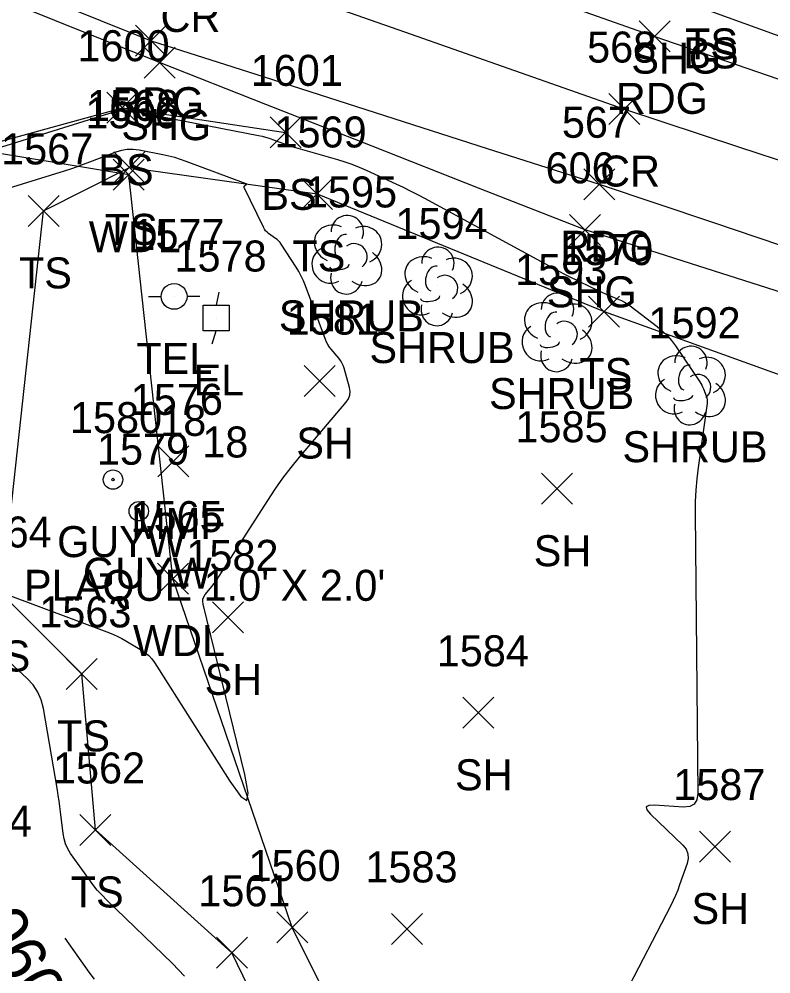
# Model space of a CAD drawing. Extents: x 1592612 to 1596497, y 111838 to 113741.
# Drawn here: x 1592925.8 to 1592974.4, y 113362.1 to 113423.7 of the extents above; entities that cross this region are included whole.
import ezdxf

# ---------------------------------------------------------------- set-up
doc = ezdxf.new("R2010")
doc.units = 0
for name, color, linetype in [('L_A', 7, 'Continuous'), ('L_C', 7, 'Continuous'), ('L_I', 7, 'Continuous'), ('L_TIC', 7, 'Continuous'), ('LAWA', 7, 'Continuous'), ('LELB', 7, 'Continuous'), ('LSH', 7, 'Continuous'), ('LSOGCMA_T', 7, 'Continuous'), ('LSOGCMI', 7, 'Continuous'), ('P_A', 7, 'Continuous'), ('P_I', 7, 'Continuous'), ('P_TIC', 7, 'Continuous'), ('PEU', 7, 'Continuous'), ('PRC', 7, 'Continuous'), ('PSU', 7, 'Continuous'), ('U_A', 7, 'Continuous'), ('U_C', 7, 'Continuous'), ('U_I', 7, 'Continuous'), ('UEPT', 7, 'Continuous'), ('UP', 7, 'Continuous'), ('UPGW', 7, 'Continuous')]:
    doc.layers.add(name, color=color, linetype=linetype)

msp = doc.modelspace()

# ---------------------------------------------------------------- linework, layer by layer
at = {"layer": 'L_TIC'}
for points in [[(1592931.512, 113416.98), (1592933.512, 113418.98)], [(1592933.512, 113416.98), (1592931.512, 113418.98)], [(1592942.04, 113415.39), (1592944.04, 113417.39)], [(1592944.04, 113415.39), (1592942.04, 113417.39)], [(1592931.961, 113413.131), (1592933.961, 113415.131)], [(1592933.961, 113413.131), (1592931.961, 113415.131)], [(1592931.916, 113412.656), (1592933.916, 113414.656)], [(1592933.916, 113412.656), (1592931.916, 113414.656)], [(1592944.073, 113411.416), (1592946.073, 113413.416)], [(1592946.073, 113411.416), (1592944.073, 113413.416)], [(1592926.418, 113410.321), (1592928.418, 113412.321)], [(1592928.418, 113410.321), (1592926.418, 113412.321)], [(1592962.598, 113403.825), (1592964.598, 113405.825)], [(1592964.598, 113403.825), (1592962.598, 113405.825)], [(1592944.244, 113399.341), (1592946.244, 113401.341)], [(1592946.244, 113399.341), (1592944.244, 113401.341)], [(1592934.794, 113394.161), (1592936.794, 113396.161)], [(1592936.794, 113394.161), (1592934.794, 113396.161)], [(1592959.57, 113392.394), (1592961.57, 113394.394)], [(1592961.57, 113392.394), (1592959.57, 113394.394)], [(1592934.771, 113386.596), (1592936.771, 113388.596)], [(1592936.771, 113386.596), (1592934.771, 113388.596)], [(1592938.327, 113384.094), (1592940.327, 113386.094)], [(1592940.327, 113384.094), (1592938.327, 113386.094)], [(1592928.879, 113380.446), (1592930.879, 113382.446)], [(1592930.879, 113380.446), (1592928.879, 113382.446)], [(1592954.49, 113377.937), (1592956.49, 113379.937)], [(1592956.49, 113377.937), (1592954.49, 113379.937)], [(1592929.763, 113370.375), (1592931.763, 113372.375)], [(1592931.763, 113370.375), (1592929.763, 113372.375)], [(1592969.755, 113369.303), (1592971.755, 113371.303)], [(1592971.755, 113369.303), (1592969.755, 113371.303)], [(1592942.474, 113364.084), (1592944.474, 113366.084)], [(1592944.474, 113364.084), (1592942.474, 113366.084)], [(1592949.886, 113363.989), (1592951.886, 113365.989)], [(1592951.886, 113363.989), (1592949.886, 113365.989)], [(1592938.58, 113362.449), (1592940.58, 113364.449)], [(1592940.58, 113362.449), (1592938.58, 113364.449)]]:
    msp.add_lwpolyline(points, dxfattribs=at)
at = {"layer": 'LAWA'}
for points in [[(1592932.916, 113413.656), (1592913.205, 113416.891)], [(1593081.556, 113298.492), (1593031.204, 113311.984), (1593004.196, 113328.084), (1592975.03, 113331.936), (1592955.15, 113341.657), (1592943.474, 113365.084), (1592935.771, 113387.596), (1592932.916, 113413.656)]]:
    msp.add_lwpolyline(points, dxfattribs=at)
at = {"layer": 'LELB'}
for points in [[(1592915.162, 113421.985), (1592920.685, 113414.734), (1592932.512, 113417.98), (1592943.04, 113416.389)], [(1593022.223, 113298.621), (1592996.05, 113319.251), (1592973.737, 113329.884), (1592951.567, 113338.734), (1592939.58, 113363.449), (1592930.763, 113371.375), (1592929.879, 113381.446), (1592924.735, 113386.602), (1592927.418, 113411.322), (1592932.961, 113414.131), (1592945.073, 113412.416), (1592963.598, 113404.825), (1592977.398, 113399.854), (1592996.446, 113393.062), (1593007.402, 113387.97)]]:
    msp.add_lwpolyline(points, dxfattribs=at)
at = {"layer": 'LSH'}
for p, q in [((1592946.979, 113408.545), (1592946.979, 113408.545)), ((1592946.979, 113408.545), (1592946.979, 113408.545)), ((1592952.825, 113406.502), (1592952.825, 113406.502)), ((1592952.825, 113406.502), (1592952.825, 113406.502)), ((1592960.546, 113403.536), (1592960.546, 113403.536)), ((1592960.546, 113403.536), (1592960.546, 113403.536)), ((1592969.157, 113400.107), (1592969.157, 113400.107)), ((1592969.157, 113400.107), (1592969.157, 113400.107))]:
    msp.add_line(p, q, dxfattribs=at)
for centre in [(1592947.025, 113409.979), (1592952.872, 113407.936), (1592960.593, 113404.97), (1592969.204, 113401.541)]:
    msp.add_arc(centre, 1.047, 335.52715, 180.95627, dxfattribs=at)
for centre, major_axis, ratio, start_param, end_param in [((1592946.187, 113409.212), (1.21, -0.512), 0.895232, 1.570796, 4.712389), ((1592948.02, 113409.129), (-1.141, -0.483), 0.949671, 1.570796, 4.712389), ((1592946.77, 113409.004), (-0.208, -0.792), 0.645439, 3.141593, 6.283185), ((1592945.895, 113407.837), (0.584, -1.042), 0.959034, 3.141593, 6.283185), ((1592947.479, 113408.379), (-0.5, 0.667), 0.989748, 3.141593, 6.283185), ((1592947.979, 113407.712), (-1.09, 0.792), 0.841452, 1.570796, 4.712389), ((1592952.033, 113407.168), (1.21, -0.512), 0.895232, 1.570796, 4.712389), ((1592953.867, 113407.085), (-1.141, -0.483), 0.949671, 1.570796, 4.712389), ((1592946.52, 113407.795), (-0.625, -0.083), 0.423636, 0, 3.141593), ((1592952.617, 113406.96), (-0.208, -0.792), 0.645439, 3.141593, 6.283185), ((1592946.979, 113407.045), (0.265, 1.061), 0.942809, 1.570796, 4.712389), ((1592953.325, 113406.335), (-0.5, 0.667), 0.989748, 3.141593, 6.283185), ((1592951.742, 113405.793), (0.584, -1.042), 0.959034, 3.141593, 6.283185), ((1592953.825, 113405.669), (-1.09, 0.792), 0.841452, 1.570796, 4.712389), ((1592952.367, 113405.752), (-0.625, -0.083), 0.423636, 0, 3.141593), ((1592952.825, 113405.002), (0.265, 1.061), 0.942809, 1.570796, 4.712389), ((1592959.754, 113404.203), (1.21, -0.512), 0.895232, 1.570796, 4.712389), ((1592961.588, 113404.12), (-1.141, -0.483), 0.949671, 1.570796, 4.712389), ((1592960.338, 113403.994), (-0.208, -0.792), 0.645439, 3.141593, 6.283185), ((1592959.463, 113402.828), (0.584, -1.042), 0.959034, 3.141593, 6.283185), ((1592961.046, 113403.369), (-0.5, 0.667), 0.989748, 3.141593, 6.283185), ((1592961.546, 113402.703), (-1.09, 0.792), 0.841452, 1.570796, 4.712389), ((1592960.088, 113402.786), (-0.625, -0.083), 0.423636, 0, 3.141593), ((1592960.546, 113402.036), (0.265, 1.061), 0.942809, 1.570796, 4.712389), ((1592968.365, 113400.773), (1.21, -0.512), 0.895232, 1.570796, 4.712389), ((1592970.198, 113400.69), (-1.141, -0.483), 0.949671, 1.570796, 4.712389), ((1592968.948, 113400.565), (-0.208, -0.792), 0.645439, 3.141593, 6.283185), ((1592969.657, 113399.94), (-0.5, 0.667), 0.989748, 3.141593, 6.283185), ((1592968.074, 113399.398), (0.584, -1.042), 0.959034, 3.141593, 6.283185), ((1592970.157, 113399.273), (-1.09, 0.792), 0.841452, 1.570796, 4.712389), ((1592968.699, 113399.357), (-0.625, -0.083), 0.423636, 0, 3.141593), ((1592969.157, 113398.607), (0.265, 1.061), 0.942809, 1.570796, 4.712389)]:
    msp.add_ellipse(centre, major_axis=major_axis, ratio=ratio, start_param=start_param, end_param=end_param, dxfattribs=at)
at = {"layer": 'LSOGCMI'}
for points in [[(1592921.676, 113414.499), (1592932.392, 113417.85), (1592932.406, 113417.854), (1592932.419, 113417.859), (1592932.432, 113417.864), (1592932.444, 113417.868), (1592932.496, 113417.888), (1592932.509, 113417.892), (1592932.522, 113417.894), (1592932.535, 113417.894), (1592932.549, 113417.893), (1592941.291, 113416.192), (1592941.521, 113416.142), (1592941.749, 113416.083), (1592941.974, 113416.015), (1592942.197, 113415.937), (1592943.081, 113415.609), (1592943.303, 113415.529), (1592943.527, 113415.453), (1592943.752, 113415.383), (1592943.978, 113415.316), (1592946.382, 113414.638), (1592946.855, 113414.494), (1592947.321, 113414.333), (1592947.781, 113414.153), (1592948.233, 113413.955), (1592950.158, 113413.069), (1592950.626, 113412.848), (1592951.091, 113412.62), (1592951.552, 113412.385), (1592952.01, 113412.142), (1592960.76, 113407.399), (1592961.008, 113407.266), (1592961.259, 113407.136), (1592961.511, 113407.009), (1592961.764, 113406.885), (1592962.889, 113406.343), (1592963.089, 113406.248), (1592963.291, 113406.155), (1592963.494, 113406.065), (1592963.698, 113405.977), (1592964.516, 113405.632), (1592964.717, 113405.539), (1592964.911, 113405.435), (1592965.098, 113405.319), (1592965.279, 113405.19), (1592967.022, 113403.869), (1592967.359, 113403.592), (1592967.669, 113403.29), (1592967.953, 113402.963), (1592968.211, 113402.611), (1592969.77, 113400.293), (1592969.838, 113400.187), (1592969.9, 113400.077), (1592969.956, 113399.965), (1592970.006, 113399.849), (1592970.195, 113399.38), (1592970.234, 113399.262), (1592970.257, 113399.142), (1592970.263, 113399.02), (1592970.254, 113398.896), (1592969.673, 113394.763), (1592969.584, 113394.032), (1592969.522, 113393.299), (1592969.488, 113392.564), (1592969.481, 113391.827), (1592969.647, 113373.731), (1592969.593, 113373.325), (1592969.42, 113373.044), (1592969.13, 113372.888), (1592968.722, 113372.856), (1592966.855, 113372.977), (1592966.488, 113372.963), (1592966.323, 113372.86), (1592966.359, 113372.669), (1592966.596, 113372.389), (1592968.678, 113370.392), (1592968.892, 113370.128), (1592969.011, 113369.842), (1592969.034, 113369.533), (1592968.961, 113369.202), (1592968.477, 113367.83), (1592968.35, 113367.489), (1592968.212, 113367.154), (1592968.062, 113366.823), (1592967.9, 113366.498), (1592961.926, 113354.979)], [(1592924.938, 113386.606), (1592931.666, 113384.097), (1592931.94, 113383.987), (1592932.209, 113383.866), (1592932.471, 113383.732), (1592932.728, 113383.586), (1592933.744, 113382.978), (1592933.986, 113382.814), (1592934.204, 113382.625), (1592934.399, 113382.412), (1592934.57, 113382.175), (1592939.44, 113374.533), (1592940.149, 113373.541), (1592940.546, 113373.279), (1592940.631, 113373.747), (1592940.405, 113374.945), (1592937.716, 113385.943), (1592937.693, 113386.111), (1592937.709, 113386.269), (1592937.762, 113386.42), (1592937.855, 113386.561), (1592938.3, 113387.11), (1592938.41, 113387.249), (1592938.515, 113387.39), (1592938.616, 113387.535), (1592938.714, 113387.682), (1592941.886, 113392.64), (1592942.366, 113393.362), (1592942.87, 113394.068), (1592943.396, 113394.756), (1592943.946, 113395.427), (1592946.958, 113398.979), (1592947.105, 113399.197), (1592947.189, 113399.429), (1592947.209, 113399.675), (1592947.165, 113399.935), (1592946.814, 113401.173), (1592946.754, 113401.348), (1592946.676, 113401.515), (1592946.581, 113401.671), (1592946.468, 113401.819), (1592945.981, 113402.389), (1592945.866, 113402.536), (1592945.765, 113402.691), (1592945.679, 113402.854), (1592945.607, 113403.026), (1592944.321, 113406.49), (1592944.195, 113406.803), (1592944.053, 113407.108), (1592943.894, 113407.404), (1592943.718, 113407.692), (1592942.764, 113409.168), (1592942.686, 113409.278), (1592942.598, 113409.378), (1592942.5, 113409.469), (1592942.393, 113409.551), (1592941.948, 113409.862), (1592941.843, 113409.945), (1592941.751, 113410.039), (1592941.672, 113410.145), (1592941.607, 113410.262), (1592940.371, 113412.838), (1592940.362, 113412.867), (1592940.363, 113412.893), (1592940.375, 113412.917), (1592940.397, 113412.938), (1592940.507, 113413.016), (1592940.527, 113413.034), (1592940.532, 113413.051), (1592940.523, 113413.066), (1592940.499, 113413.078), (1592936.628, 113414.515), (1592936.259, 113414.644), (1592935.885, 113414.757), (1592935.506, 113414.855), (1592935.124, 113414.938), (1592933.584, 113415.237), (1592933.202, 113415.285), (1592932.824, 113415.28), (1592932.45, 113415.22), (1592932.082, 113415.107), (1592930.39, 113414.459), (1592929.985, 113414.308), (1592929.577, 113414.163), (1592929.168, 113414.024), (1592928.756, 113413.892), (1592925.127, 113412.757)], [(1592936.521, 113361.95), (1592935.734, 113362.757), (1592931.51, 113366.841), (1592931.192, 113367.164), (1592930.889, 113367.5), (1592930.603, 113367.851), (1592930.333, 113368.215), (1592929.167, 113369.863), (1592928.984, 113370.16), (1592928.841, 113370.472), (1592928.738, 113370.8), (1592928.677, 113371.144), (1592928.513, 113372.549), (1592928.469, 113372.9), (1592928.421, 113373.251), (1592928.368, 113373.6), (1592928.311, 113373.949), (1592927.406, 113379.214), (1592927.266, 113379.768), (1592927.043, 113380.276), (1592926.738, 113380.739), (1592926.35, 113381.157), (1592924.632, 113382.741)], [(1592928.801, 113364.386), (1592930.343, 113362.204), (1592930.685, 113361.744)]]:
    msp.add_lwpolyline(points, dxfattribs=at)
at = {"layer": 'P_TIC'}
for points in [[(1592965.871, 113421.584), (1592967.871, 113423.584)], [(1592967.871, 113421.584), (1592965.871, 113423.584)], [(1592933.357, 113421.305), (1592935.357, 113423.305)], [(1592935.357, 113421.305), (1592933.357, 113423.305)], [(1592933.904, 113419.887), (1592935.904, 113421.887)], [(1592935.904, 113419.887), (1592933.904, 113421.887)], [(1592963.913, 113416.893), (1592965.913, 113418.893)], [(1592965.913, 113416.893), (1592963.913, 113418.893)], [(1592962.287, 113412.04), (1592964.287, 113414.04)], [(1592964.287, 113412.04), (1592962.287, 113414.04)], [(1592961.368, 113409.099), (1592963.368, 113411.099)], [(1592963.368, 113409.099), (1592961.368, 113411.099)]]:
    msp.add_lwpolyline(points, dxfattribs=at)
at = {"layer": 'PEU'}
for points in [[(1592911.508, 113442.333), (1592918.265, 113439.915), (1592925.029, 113437.495), (1592931.793, 113435.074), (1592938.557, 113432.654), (1592945.636, 113430.136), (1592952.714, 113427.619), (1592959.793, 113425.101), (1592966.871, 113422.584), (1592974.123, 113420.081), (1592981.374, 113417.579), (1592988.626, 113415.076), (1592995.877, 113412.574), (1593003.018, 113410.299), (1593010.16, 113408.025)], [(1592908.287, 113432.828), (1592914.737, 113430.225), (1592921.277, 113427.585), (1592927.817, 113424.945), (1592934.357, 113422.305), (1592941.59, 113419.989), (1592948.822, 113417.672), (1592956.055, 113415.356), (1592963.287, 113413.04), (1592970.605, 113410.585), (1592977.923, 113408.13), (1592985.241, 113405.675), (1592992.559, 113403.22), (1592999.818, 113401.035), (1593007.077, 113398.85)]]:
    msp.add_lwpolyline(points, dxfattribs=at)
at = {"layer": 'PRC'}
msp.add_lwpolyline([(1592910.112, 113438.221), (1592916.699, 113435.64), (1592923.312, 113433.05), (1592929.925, 113430.459), (1592936.538, 113427.868), (1592943.632, 113425.375), (1592950.725, 113422.881), (1592957.819, 113420.387), (1592964.913, 113417.893), (1592972.273, 113415.465), (1592979.633, 113413.038), (1592986.992, 113410.61), (1592994.352, 113408.182), (1593001.474, 113405.968), (1593008.597, 113403.754)], dxfattribs=at)
at = {"layer": 'PSU'}
for points in [[(1593167.681, 113369.582), (1593139.7, 113376.255), (1593109.821, 113382.695), (1593081.736, 113389.175), (1593053.818, 113397.152), (1593024.821, 113405.619), (1592996.75, 113414.705), (1592967.822, 113425.179), (1592940.197, 113435.636), (1592911.843, 113443.034)], [(1593006.031, 113395.756), (1592998.904, 113398.23), (1592991.777, 113400.703), (1592984.424, 113403.052), (1592977.072, 113405.401), (1592969.72, 113407.75), (1592962.368, 113410.099), (1592955.502, 113412.796), (1592948.636, 113415.493), (1592941.77, 113418.19), (1592934.904, 113420.887), (1592928.153, 113423.606), (1592921.403, 113426.325), (1592914.652, 113429.044), (1592907.917, 113431.757)]]:
    msp.add_lwpolyline(points, dxfattribs=at)
at = {"layer": 'UEPT'}
for p, q in [((1592938.727, 113406.077), (1592938.56, 113405.243)), ((1592937.727, 113403.577), (1592937.727, 113405.243)), ((1592937.727, 113405.243), (1592939.393, 113405.243)), ((1592939.393, 113405.243), (1592939.393, 113403.577)), ((1592938.56, 113404.41), (1592938.56, 113404.41)), ((1592939.393, 113403.577), (1592937.727, 113403.577)), ((1592938.31, 113402.743), (1592938.56, 113403.577))]:
    msp.add_line(p, q, dxfattribs=at)
at = {"layer": 'UP'}
for p, q in [((1592934.186, 113405.799), (1592935.012, 113405.799)), ((1592935.845, 113405.804), (1592935.845, 113405.804)), ((1592937.512, 113405.804), (1592936.679, 113405.804)), ((1592936.679, 113405.804), (1592936.679, 113405.804)), ((1592937.512, 113405.804), (1592937.512, 113405.804))]:
    msp.add_line(p, q, dxfattribs=at)
msp.add_circle((1592935.845, 113405.804), 0.833, dxfattribs=at)
at = {"layer": 'UPGW'}
for centre, radius in [((1592931.9, 113393.982), 0.625), ((1592931.9, 113393.982), 0.0833), ((1592933.564, 113391.945), 0.625), ((1592933.564, 113391.945), 0.0833)]:
    msp.add_circle(centre, radius, dxfattribs=at)

# ---------------------------------------------------------------- texts
at = {"layer": 'L_A'}
for s, p in [('TS', (1592968.825, 113421.097)), ('BS', (1592968.721, 113420.515)), ('BS', (1592930.953, 113412.98)), ('BS', (1592941.481, 113411.39)), ('WDL', (1592930.334, 113408.656)), ('TS', (1592931.37, 113409.131)), ('TS', (1592943.483, 113407.416)), ('TS', (1592925.828, 113406.321)), ('SHRUB', (1592942.608, 113403.545)), ('SHRUB', (1592948.455, 113401.502)), ('TS', (1592962.007, 113399.825)), ('SHRUB', (1592956.176, 113398.536)), ('SH', (1592943.732, 113395.341)), ('SHRUB', (1592964.787, 113395.107)), ('MMF', (1592933.077, 113390.161)), ('SH', (1592959.058, 113388.394)), ('WDL', (1592933.189, 113382.596)), ('TS', (1592923.144, 113381.602)), ('SH', (1592937.815, 113380.094)), ('TS', (1592928.288, 113376.446)), ('SH', (1592953.978, 113373.937)), ('TS', (1592929.173, 113366.375)), ('SH', (1592969.243, 113365.303))]:
    msp.add_text(s, height=2, dxfattribs=at).set_placement(p)
at = {"layer": 'L_C'}
msp.add_text("WWII PLAQUE 1.0' X 2.0'", height=2, dxfattribs=at).set_placement((1592918.88, 113386.161))
at = {"layer": 'L_I'}
for s, p in [('1600', (1592929.606, 113420.98)), ('1601', (1592940.788, 113419.39)), ('1566', (1592930.121, 113416.656)), ('1568', (1592930.221, 113417.131)), ('1569', (1592942.325, 113415.416)), ('1567', (1592924.678, 113414.321)), ('1595', (1592944.286, 113411.545)), ('1594', (1592950.132, 113409.502)), ('1570', (1592960.818, 113407.825)), ('1593', (1592957.853, 113406.536)), ('1581', (1592943.118, 113403.341)), ('1592', (1592966.464, 113403.107)), ('1576', (1592933.046, 113398.161)), ('1585', (1592957.877, 113396.394)), ('1565', (1592933.031, 113390.596)), ('1564', (1592921.995, 113389.602)), ('1582', (1592936.634, 113388.094)), ('1563', (1592927.139, 113384.446)), ('1584', (1592952.797, 113381.937)), ('1562', (1592928.023, 113374.375)), ('1587', (1592968.062, 113373.303)), ('1454', (1592920.718, 113370.949)), ('1560', (1592940.647, 113368.084)), ('1583', (1592948.193, 113367.989)), ('1561', (1592937.407, 113366.449))]:
    msp.add_text(s, height=2, dxfattribs=at).set_placement(p)
at = {"layer": 'LSOGCMA_T'}
msp.add_text('1060', height=3, rotation=299.71155, dxfattribs=at).set_placement((1592921.995, 113367.233))
at = {"layer": 'P_A'}
for s, p in [('CR', (1592934.971, 113422.868)), ('SHG', (1592965.358, 113420.18)), ('RDG', (1592931.846, 113417.305)), ('RDG', (1592964.359, 113417.584)), ('SHG', (1592932.439, 113415.887)), ('CR', (1592963.346, 113412.893)), ('RDG', (1592960.775, 113408.04)), ('SHG', (1592959.903, 113405.099))]:
    msp.add_text(s, height=2, dxfattribs=at).set_placement(p)
at = {"layer": 'P_I'}
for s, p in [('568', (1592962.504, 113420.893)), ('567', (1592960.877, 113416.04)), ('606', (1592959.824, 113413.099))]:
    msp.add_text(s, height=2, dxfattribs=at).set_placement(p)
at = {"layer": 'U_A'}
for s, p in [('TEL', (1592933.405, 113400.804)), ('EL', (1592937.096, 113399.41)), ('GUYW', (1592928.293, 113388.982)), ('GUYW', (1592929.958, 113386.945))]:
    msp.add_text(s, height=2, dxfattribs=at).set_placement(p)
at = {"layer": 'U_C'}
for p in [(1592934.948, 113396.804), (1592937.662, 113395.41)]:
    msp.add_text('18', height=2, dxfattribs=at).set_placement(p)
at = {"layer": 'U_I'}
for s, p in [('1577', (1592933.153, 113408.804)), ('1578', (1592935.867, 113407.41)), ('1580', (1592929.12, 113396.982)), ('1579', (1592930.864, 113394.945))]:
    msp.add_text(s, height=2, dxfattribs=at).set_placement(p)

doc.saveas('drawing.dxf')
